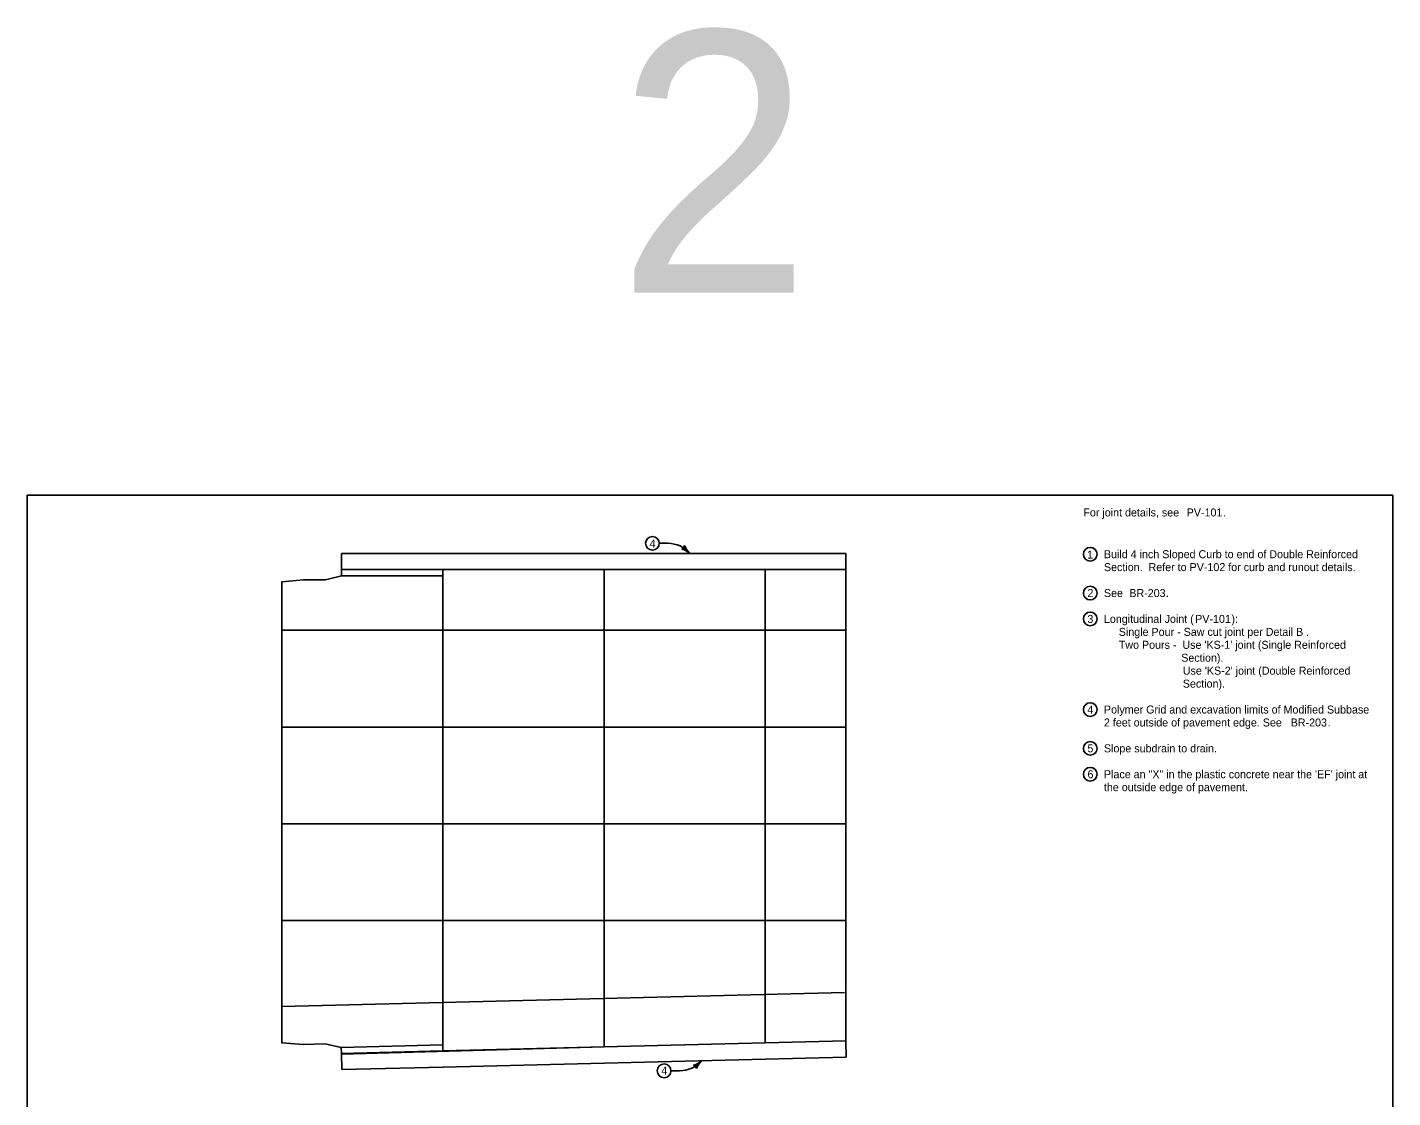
# Model space of a CAD drawing. Extents: x 10045 to 81668, y 6370 to 11018.
# Drawn here: x 13733 to 16868, y 8561 to 11018 of the extents above; entities that cross this region are included whole.
import ezdxf

# ---------------------------------------------------------------- set-up
doc = ezdxf.new("R2010")
doc.units = 0
for name, color, linetype in [('Alignment', 7, 'Continuous'), ('dsnStdLineWork', 7, 'Continuous'), ('LaneLine', 7, 'Continuous'), ('Level 5', 7, 'Continuous'), ('PC_APPROACH', 7, 'Continuous'), ('SheetText', 7, 'Continuous'), ('TextAlignmentLrg', 7, 'Continuous'), ('TextAlignmentSml', 7, 'Continuous')]:
    doc.layers.add(name, color=color, linetype=linetype)

msp = doc.modelspace()

# ---------------------------------------------------------------- linework, layer by layer
at = {"layer": 'Alignment'}
for p, q in [((15203.3, 9833.7), (15183.4, 9833.7)), ((15210.5, 8622.9), (15230.3, 8622.9))]:
    msp.add_line(p, q, dxfattribs=at)
for centre, start, end in [((15203.3, 9766.9), 40.5607, 90), ((15203.3, 9766.9), 40.5607, 90), ((15230.3, 8689.7), 270, 319.4393), ((15230.3, 8689.7), 270, 319.4393)]:
    msp.add_arc(centre, 66.8, start, end, dxfattribs=at)
at = {"layer": 'dsnStdLineWork'}
for p, q in [((14453.9, 9810.3), (14686.8, 9810.3)), ((14453.9, 9810.3), (14453.9, 9773.3)), ((14686.8, 9810.3), (15611.9, 9810.3)), ((15611.9, 9810.3), (15611.9, 9773.3)), ((15612.9, 8654.6), (15611.9, 8691.6)), ((14454.8, 8625.7), (14453.8, 8662.6)), ((15612.9, 8654.6), (14687.7, 8631.5)), ((14688, 8631.5), (14454.8, 8625.7))]:
    msp.add_line(p, q, dxfattribs=at)
for points in [[(14316.7, 9745.2), (14316.7, 8687.4), (14366.5, 8683.6), (14416.3, 8684.9), (14453.5, 8676.5), (14453.8, 8662.6), (14686.8, 8668.5), (14686.8, 9773.3), (14453.9, 9773.3), (14453.9, 9759.4), (14416.9, 9750.2), (14366.8, 9750.2)], [(15056.8, 9773.3), (15056.8, 8677.7), (15611.9, 8691.6), (15611.9, 9773.3), (15149.4, 9773.3)]]:
    msp.add_lwpolyline(points, close=True, dxfattribs=at)
for centre in [(15167.7, 9833.7), (15167.7, 9833.7), (16173, 9808.8), (16173, 9719.6), (16173, 9660.2), (16173, 9452.2), (16173, 9363.1), (16173, 9303.7), (15194.7, 8622.9), (15194.7, 8622.9)]:
    msp.add_circle(centre, 15.7, dxfattribs=at)
for centre, radius, start, end in [((15226.7, 9835.6), 17.1, 299.4947, 334.9614), ((15226.7, 9835.6), 17.1, 299.4947, 334.9614), ((15223.9, 9777.7), 44.4, 47.2281, 75.3006), ((15223.9, 9777.7), 44.4, 47.2281, 75.3006), ((15284.2, 9842.9), 44.4, 199.1556, 227.2281), ((15284.2, 9842.9), 44.4, 199.1556, 227.2281), ((15250.9, 8678.9), 44.4, 284.6994, 312.7719), ((15250.9, 8678.9), 44.4, 284.6994, 312.7719), ((15253.8, 8621), 17.1, 25.0386, 60.5053), ((15253.8, 8621), 17.1, 25.0386, 60.5053), ((15311.2, 8613.7), 44.4, 132.7719, 160.8444), ((15311.2, 8613.7), 44.4, 132.7719, 160.8444)]:
    msp.add_arc(centre, radius, start, end, dxfattribs=at)
at = {"layer": 'LaneLine'}
msp.add_lwpolyline([(14316.7, 9745.2), (14316.7, 8687.4), (14366.5, 8683.6), (14416.3, 8684.9), (14453.5, 8676.5), (14453.9, 8661.5), (15056.8, 8677.7), (15056.8, 9773.3), (14453.9, 9773.3), (14453.9, 9759.4), (14416.9, 9750.2), (14366.8, 9750.2)], close=True, dxfattribs=at)
at = {"layer": 'Level 5'}
msp.add_lwpolyline([(13732.5, 9944), (16867.5, 9944), (16867.5, 7924), (13732.5, 7924)], close=True, dxfattribs=at)
at = {"layer": 'PC_APPROACH'}
for p, q in [((14453.9, 9759.4), (14453.9, 9773.3)), ((14686.8, 9773.3), (15611.9, 9773.3)), ((15611.9, 9773.3), (15611.9, 8691.6)), ((14316.7, 9745.2), (14316.7, 8687.4)), ((15611.9, 8691.6), (14686.8, 8668.5))]:
    msp.add_line(p, q, dxfattribs=at)
for points in [[(14453.9, 9759.4), (14416.9, 9750.2), (14366.8, 9750.2), (14316.7, 9745.2)], [(14316.7, 8687.4), (14366.5, 8683.6), (14416.3, 8684.9), (14453.5, 8676.5), (14453.9, 8661.5)]]:
    msp.add_lwpolyline(points, dxfattribs=at)
at = {"layer": 'TextAlignmentLrg'}
for p, q in [((14686.8, 9773.3), (14686.8, 8668.5)), ((15056.8, 9773.3), (15056.8, 8677.7)), ((15426.9, 9773.3), (15426.9, 8687)), ((14316.7, 9634.2), (15611.9, 9634.2)), ((14316.7, 9412.1), (15611.9, 9412.1)), ((14316.7, 9190.1), (15611.9, 9190.1)), ((14316.7, 8968), (15611.9, 8968)), ((15609.2, 8802.6), (14316.7, 8770.3))]:
    msp.add_line(p, q, dxfattribs=at)
at = {"layer": 'TextAlignmentSml'}
for p, q in [((14453.9, 9773.3), (14686.8, 9773.3)), ((14453.9, 9759.4), (14686.8, 9759.4)), ((14686.8, 9759.4), (14686.8, 9773.3)), ((14686.8, 8682.3), (14453.5, 8676.5)), ((14687.1, 8668.5), (14453.8, 8662.6)), ((14686.8, 8682.3), (14686.8, 8668.5))]:
    msp.add_line(p, q, dxfattribs=at)

# ---------------------------------------------------------------- texts
at = {"layer": 'Alignment'}
for s, height, p in [('For joint details, see ', 18.375, (16157.3, 9895.4)), ('PV-101', 18.37, (16394.5, 9895.4)), ('PV-101', 18.37, (16394.5, 9895.4)), ('.', 18.4, (16477.7, 9895.4)), ('4', 18.4, (15161.3, 9823.8)), ('4', 18.4, (15161.3, 9823.8)), ('1', 18.4, (16165.8, 9798.5)), ('Build 4 inch Sloped Curb to end of Double Reinforced', 18.375, (16204.5, 9799.6)), ('Section.  Refer to PV-102 for curb and runout details.', 18.375, (16204.5, 9769.9)), ('2', 18.4, (16166.8, 9710.4)), ('See ', 18.37, (16204.5, 9710.4)), ('BR-203.', 18.37, (16262.8, 9710.4)), ('.', 18.4, (16347.4, 9710.4)), ('3', 18.4, (16166.6, 9651)), ('Longitudinal Joint (', 18.375, (16204.5, 9651)), ('PV-101', 18.37, (16414, 9651)), ('PV-101', 18.37, (16414, 9651)), ('):', 18.37, (16497.3, 9651)), ('     Single Pour - Saw cut joint per Detail B .', 18.375, (16204.5, 9621.3)), ("     Two Pours -  Use 'KS-1' joint (Single Reinforced", 18.375, (16204.5, 9591.6)), ('                          Section).', 18.375, (16204.5, 9561.9)), ("     Use 'KS-2' joint (Double Reinforced", 18.375, (16351.5, 9532.2)), ('     Section).', 18.375, (16351.5, 9502.5)), ('4', 18.4, (16166.6, 9443)), ('Polymer Grid and excavation limits of Modified Subbase', 18.375, (16204.5, 9443)), ('2 feet outside of pavement edge. See ', 18.375, (16204.5, 9413.3)), ('BR-203', 18.37, (16633.3, 9413.3)), ('.', 18.4, (16717.9, 9413.3)), ('5', 18.4, (16166.6, 9353.9)), ('Slope subdrain to drain.', 18.375, (16204.5, 9353.9)), ('6', 18.4, (16166.8, 9294.5)), ('Place an "X" in the plastic concrete near the \'EF\' joint at', 18.375, (16204.5, 9294.5)), ('the outside edge of pavement.', 18.375, (16204.5, 9264.8)), ('4', 18.4, (15188.3, 8614.4)), ('4', 18.4, (15188.3, 8614.4))]:
    msp.add_text(s, height=height, dxfattribs=at).set_placement(p)
at = {"layer": 'SheetText'}
msp.add_text('2', height=600, dxfattribs=at).set_placement((15085.9, 10409.2))

doc.saveas('drawing.dxf')
